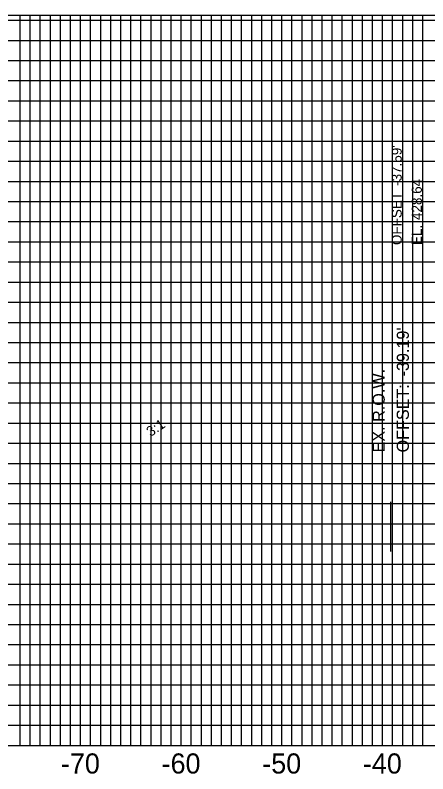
# Model space of a CAD drawing. Extents: x -158 to 158, y 398 to 482.
# Drawn here: x -76.5 to -35.5, y 402.2 to 477.5 of the extents above; entities that cross this region are included whole.
import ezdxf

# ---------------------------------------------------------------- set-up
doc = ezdxf.new("R2010")
doc.units = 0
for name, color, linetype in [('AERIAL - Automatic - Grid Points', 7, 'Continuous'), ('DES - CL - Proposed Text', 7, 'Continuous'), ('DES - SCRATCH - User 1', 7, 'Continuous'), ('DES - SHEET - Corner Text', 7, 'Continuous'), ('DES - SHEET - Revision Text', 7, 'Continuous')]:
    doc.layers.add(name, color=color, linetype=linetype)

msp = doc.modelspace()

# ---------------------------------------------------------------- linework, layer by layer
at = {"layer": 'AERIAL - Automatic - Grid Points'}
msp.add_line((-39.186, 424.244), (-39.186, 429.164), dxfattribs=at)
msp.add_line((-39.186, 424.244), (-39.186, 429.164), dxfattribs=at)
msp.add_line((-39.186, 424.244), (-39.186, 429.164), dxfattribs=at)
msp.add_line((-39.186, 424.244), (-39.186, 429.164), dxfattribs=at)
at = {"layer": 'DES - SCRATCH - User 1'}
for p, q in [((-150, 477.499), (150, 477.499)), ((-150, 477.499), (150, 477.499)), ((-150, 477.499), (150, 477.499)), ((-70, 405), (-70, 477.499)), ((-70, 405), (-70, 477.499)), ((-70, 405), (-70, 477.499)), ((-60, 405), (-60, 477.499)), ((-60, 405), (-60, 477.499)), ((-60, 405), (-60, 477.499)), ((-50, 405), (-50, 477.499)), ((-50, 405), (-50, 477.499)), ((-50, 405), (-50, 477.499)), ((-40, 405), (-40, 477.499)), ((-40, 405), (-40, 477.499)), ((-40, 405), (-40, 477.499)), ((-150, 475), (150, 475)), ((-150, 475), (150, 475)), ((-150, 475), (150, 475)), ((-150, 455), (150, 455)), ((-150, 455), (150, 455)), ((-150, 455), (150, 455)), ((-150, 435), (150, 435)), ((-150, 435), (150, 435)), ((-150, 435), (150, 435)), ((-150, 415), (150, 415)), ((-150, 415), (150, 415)), ((-150, 415), (150, 415)), ((-150, 405), (150, 405)), ((-150, 405), (150, 405)), ((-150, 405), (150, 405))]:
    msp.add_line(p, q, dxfattribs=at)
at = {"layer": 'DES - SHEET - Corner Text'}
for p, q in [((-150, 477), (150, 477)), ((-150, 477), (150, 477)), ((-150, 477), (150, 477)), ((-76, 405), (-76, 477.499)), ((-76, 405), (-76, 477.499)), ((-76, 405), (-76, 477.499)), ((-75, 405), (-75, 477.499)), ((-75, 405), (-75, 477.499)), ((-75, 405), (-75, 477.499)), ((-74, 405), (-74, 477.499)), ((-74, 405), (-74, 477.499)), ((-74, 405), (-74, 477.499)), ((-73, 405), (-73, 477.499)), ((-73, 405), (-73, 477.499)), ((-73, 405), (-73, 477.499)), ((-72, 405), (-72, 477.499)), ((-72, 405), (-72, 477.499)), ((-72, 405), (-72, 477.499)), ((-71, 405), (-71, 477.499)), ((-71, 405), (-71, 477.499)), ((-71, 405), (-71, 477.499)), ((-69, 405), (-69, 477.499)), ((-69, 405), (-69, 477.499)), ((-69, 405), (-69, 477.499)), ((-68, 405), (-68, 477.499)), ((-68, 405), (-68, 477.499)), ((-68, 405), (-68, 477.499)), ((-67, 405), (-67, 477.499)), ((-67, 405), (-67, 477.499)), ((-67, 405), (-67, 477.499)), ((-66, 405), (-66, 477.499)), ((-66, 405), (-66, 477.499)), ((-66, 405), (-66, 477.499)), ((-65, 405), (-65, 477.499)), ((-65, 405), (-65, 477.499)), ((-65, 405), (-65, 477.499)), ((-64, 405), (-64, 477.499)), ((-64, 405), (-64, 477.499)), ((-64, 405), (-64, 477.499)), ((-63, 405), (-63, 477.499)), ((-63, 405), (-63, 477.499)), ((-63, 405), (-63, 477.499)), ((-62, 405), (-62, 477.499)), ((-62, 405), (-62, 477.499)), ((-62, 405), (-62, 477.499)), ((-61, 405), (-61, 477.499)), ((-61, 405), (-61, 477.499)), ((-61, 405), (-61, 477.499)), ((-59, 405), (-59, 477.499)), ((-59, 405), (-59, 477.499)), ((-59, 405), (-59, 477.499)), ((-58, 405), (-58, 477.499)), ((-58, 405), (-58, 477.499)), ((-58, 405), (-58, 477.499)), ((-57, 405), (-57, 477.499)), ((-57, 405), (-57, 477.499)), ((-57, 405), (-57, 477.499)), ((-56, 405), (-56, 477.499)), ((-56, 405), (-56, 477.499)), ((-56, 405), (-56, 477.499)), ((-55, 405), (-55, 477.499)), ((-55, 405), (-55, 477.499)), ((-55, 405), (-55, 477.499)), ((-54, 405), (-54, 477.499)), ((-54, 405), (-54, 477.499)), ((-54, 405), (-54, 477.499)), ((-53, 405), (-53, 477.499)), ((-53, 405), (-53, 477.499)), ((-53, 405), (-53, 477.499)), ((-52, 405), (-52, 477.499)), ((-52, 405), (-52, 477.499)), ((-52, 405), (-52, 477.499)), ((-51, 405), (-51, 477.499)), ((-51, 405), (-51, 477.499)), ((-51, 405), (-51, 477.499)), ((-49, 405), (-49, 477.499)), ((-49, 405), (-49, 477.499)), ((-49, 405), (-49, 477.499)), ((-48, 405), (-48, 477.499)), ((-48, 405), (-48, 477.499)), ((-48, 405), (-48, 477.499)), ((-47, 405), (-47, 477.499)), ((-47, 405), (-47, 477.499)), ((-47, 405), (-47, 477.499)), ((-46, 405), (-46, 477.499)), ((-46, 405), (-46, 477.499)), ((-46, 405), (-46, 477.499)), ((-45, 405), (-45, 477.499)), ((-45, 405), (-45, 477.499)), ((-45, 405), (-45, 477.499)), ((-44, 405), (-44, 477.499)), ((-44, 405), (-44, 477.499)), ((-44, 405), (-44, 477.499)), ((-43, 405), (-43, 477.499)), ((-43, 405), (-43, 477.499)), ((-43, 405), (-43, 477.499)), ((-42, 405), (-42, 477.499)), ((-42, 405), (-42, 477.499)), ((-42, 405), (-42, 477.499)), ((-41, 405), (-41, 477.499)), ((-41, 405), (-41, 477.499)), ((-41, 405), (-41, 477.499)), ((-39, 405), (-39, 477.499)), ((-39, 405), (-39, 477.499)), ((-39, 405), (-39, 477.499)), ((-38, 405), (-38, 477.499)), ((-38, 405), (-38, 477.499)), ((-38, 405), (-38, 477.499)), ((-37, 405), (-37, 477.499)), ((-37, 405), (-37, 477.499)), ((-37, 405), (-37, 477.499)), ((-36, 405), (-36, 477.499)), ((-36, 405), (-36, 477.499)), ((-36, 405), (-36, 477.499)), ((-150, 473), (150, 473)), ((-150, 473), (150, 473)), ((-150, 473), (150, 473)), ((-150, 471), (150, 471)), ((-150, 471), (150, 471)), ((-150, 471), (150, 471)), ((-150, 469), (150, 469)), ((-150, 469), (150, 469)), ((-150, 469), (150, 469)), ((-150, 467), (150, 467)), ((-150, 467), (150, 467)), ((-150, 467), (150, 467)), ((-150, 465), (150, 465)), ((-150, 465), (150, 465)), ((-150, 465), (150, 465)), ((-150, 463), (150, 463)), ((-150, 463), (150, 463)), ((-150, 463), (150, 463)), ((-150, 461), (150, 461)), ((-150, 461), (150, 461)), ((-150, 461), (150, 461)), ((-150, 459), (150, 459)), ((-150, 459), (150, 459)), ((-150, 459), (150, 459)), ((-150, 457), (150, 457)), ((-150, 457), (150, 457)), ((-150, 457), (150, 457)), ((-150, 453), (150, 453)), ((-150, 453), (150, 453)), ((-150, 453), (150, 453)), ((-150, 451), (150, 451)), ((-150, 451), (150, 451)), ((-150, 451), (150, 451)), ((-150, 449), (150, 449)), ((-150, 449), (150, 449)), ((-150, 449), (150, 449)), ((-150, 447), (150, 447)), ((-150, 447), (150, 447)), ((-150, 447), (150, 447)), ((-150, 445), (150, 445)), ((-150, 445), (150, 445)), ((-150, 445), (150, 445)), ((-150, 443), (150, 443)), ((-150, 443), (150, 443)), ((-150, 443), (150, 443)), ((-150, 441), (150, 441)), ((-150, 441), (150, 441)), ((-150, 441), (150, 441)), ((-150, 439), (150, 439)), ((-150, 439), (150, 439)), ((-150, 439), (150, 439)), ((-150, 437), (150, 437)), ((-150, 437), (150, 437)), ((-150, 437), (150, 437)), ((-150, 433), (150, 433)), ((-150, 433), (150, 433)), ((-150, 433), (150, 433)), ((-150, 431), (150, 431)), ((-150, 431), (150, 431)), ((-150, 431), (150, 431)), ((-150, 429), (150, 429)), ((-150, 429), (150, 429)), ((-150, 429), (150, 429)), ((-150, 427), (150, 427)), ((-150, 427), (150, 427)), ((-150, 427), (150, 427)), ((-150, 425), (150, 425)), ((-150, 425), (150, 425)), ((-150, 425), (150, 425)), ((-150, 423), (150, 423)), ((-150, 423), (150, 423)), ((-150, 423), (150, 423)), ((-150, 421), (150, 421)), ((-150, 421), (150, 421)), ((-150, 421), (150, 421)), ((-150, 419), (150, 419)), ((-150, 419), (150, 419)), ((-150, 419), (150, 419)), ((-150, 417), (150, 417)), ((-150, 417), (150, 417)), ((-150, 417), (150, 417)), ((-150, 413), (150, 413)), ((-150, 413), (150, 413)), ((-150, 413), (150, 413)), ((-150, 411), (150, 411)), ((-150, 411), (150, 411)), ((-150, 411), (150, 411)), ((-150, 409), (150, 409)), ((-150, 409), (150, 409)), ((-150, 409), (150, 409)), ((-150, 407), (150, 407)), ((-150, 407), (150, 407)), ((-150, 407), (150, 407))]:
    msp.add_line(p, q, dxfattribs=at)

# ---------------------------------------------------------------- texts
at = {"layer": 'AERIAL - Automatic - Grid Points'}
for s, p in [("-39.19'", (-37.386, 441.63)), ("-39.19'", (-37.386, 441.63)), ("-39.19'", (-37.386, 441.63)), ("-39.19'", (-37.386, 441.63)), ('EX. R.O.W. ', (-39.786, 434.084)), ('EX. R.O.W. ', (-39.786, 434.084)), ('EX. R.O.W. ', (-39.786, 434.084)), ('EX. R.O.W. ', (-39.786, 434.084)), ('OFFSET: ', (-37.386, 434.084)), ('OFFSET: ', (-37.386, 434.084)), ('OFFSET: ', (-37.386, 434.084)), ('OFFSET: ', (-37.386, 434.084))]:
    msp.add_text(s, height=1.2, rotation=90, dxfattribs=at).set_placement(p)
at = {"layer": 'DES - CL - Proposed Text'}
msp.add_text('3:1', height=1, rotation=33.68742, dxfattribs=at).set_placement((-63.041, 435.611))
msp.add_text('3:1', height=1, rotation=33.68742, dxfattribs=at).set_placement((-63.041, 435.611))
msp.add_text('3:1', height=1, rotation=33.68742, dxfattribs=at).set_placement((-63.041, 435.611))
at = {"layer": 'DES - SHEET - Revision Text'}
for s, p in [("-37.59'", (-38.094, 460.549)), ('428.64', (-36.094, 457.158)), ('OFFSET ', (-38.094, 454.674)), ('EL. ', (-36.094, 454.674))]:
    msp.add_text(s, height=1, rotation=90, dxfattribs=at).set_placement(p)
for s, p in [('-70', (-71.951, 402.2)), ('-70', (-71.951, 402.2)), ('-70', (-71.951, 402.2)), ('-60', (-61.951, 402.2)), ('-60', (-61.951, 402.2)), ('-60', (-61.951, 402.2)), ('-50', (-51.951, 402.2)), ('-50', (-51.951, 402.2)), ('-50', (-51.951, 402.2)), ('-40', (-41.951, 402.2)), ('-40', (-41.951, 402.2)), ('-40', (-41.951, 402.2))]:
    msp.add_text(s, height=2, dxfattribs=at).set_placement(p)

doc.saveas('drawing.dxf')
